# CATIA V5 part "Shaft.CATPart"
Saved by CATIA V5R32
Part number: Part4
Bounding box of the stored display mesh (mm): x -10 to 60, y -9 to 9, z 0 to 55
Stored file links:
  D:\PROJECTS\Project 2022\CATIA V5 6R 2022\Resources\Part Files\c16_catia_v5_6r2022_prt\Gear Joint-(16-53)\Shaft.CATPart
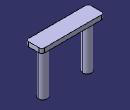
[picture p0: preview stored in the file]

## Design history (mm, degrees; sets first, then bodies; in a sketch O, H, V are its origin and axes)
Body1 (main body)
  Sketch1 on xy-plane, origin (0, 0, 0), H (1, 0, 0), V (0, 1, 0)
    circle A1 centre (0, 0) radius 5
    point P1 (30.2964, -4.0836)
    circle A2 centre (50, 0) radius 5
    point P2 (50, 0)
    radius A1 = 5
    radius A2 = 5
    distance P2 O = 50
    coincidence: P2 H
  Pad1: profile Sketch1, direction (0, 0, 1), length 50
  Sketch2 on end face of Pad1, origin (0, 0, 50), H (1, 0, 0), V (0, 1, 0)
    line L1 (-10, 9) -> (60, 9)
    line L2 (60, 9) -> (60, -9)
    line L3 (60, -9) -> (-10, -9)
    line L4 (-10, -9) -> (-10, 9)
    length L2 = 18
    distance L3 H = 9
    length L1 = 70
    distance L4 V = 10
    horizontal: L1 H, L3 H
    vertical: L2 V, L4 V
  Pad2: profile Sketch2, direction (0, 0, 1), length 5
  Fillet1: radius 3, on edge [face of Pad1 from Sketch1.A1 | start face of Pad2]; edge [face of Pad1 from Sketch1.A2 | start face of Pad2]
  Fillet2: radius 3, on edge [face of Pad2 from Sketch2.L4 | face of Pad2 from Sketch2.L1]; edge [face of Pad2 from Sketch2.L3 | face of Pad2 from Sketch2.L4]; edge [face of Pad2 from Sketch2.L1 | face of Pad2 from Sketch2.L2]; edge [face of Pad2 from Sketch2.L2 | face of Pad2 from Sketch2.L3]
